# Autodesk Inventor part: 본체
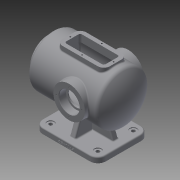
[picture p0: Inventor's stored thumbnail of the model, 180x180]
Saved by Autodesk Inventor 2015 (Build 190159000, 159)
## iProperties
Created: 2021-11
Part Number: 본체
Material: 일반
Document SubType Name: Modeling
Designer: 10259o
Density: 1 g/cm^3
Appearance: 기본값
Author: 10259o
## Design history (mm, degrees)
sketch "스케치1"
  geometry: L1 (80, -65)-(-80, -65); L2 (-80, -65)-(-80, 65); L3 (-80, 65)-(80, 65); L4 (80, 65)-(80, -65); L5 (80, -65)-(-80, 65); L6 (-80, -65)-(80, 65); 1 further point
  constraints: 12 end point, 2 midpoint, 2 parallel, 1 horizontal, 1 perpendicular
  dimensions: "d0" = 160 distance of L1.start L1.end; "d1" = 130 distance of L3.end L1.start
extrude "돌출1" new body sketch "스케치1" distance "d2" = 14; taper "d3" = 0 deg
sketch "스케치10"
  geometry: L1 (0, 0)-(0, 14) reference; 2 further points
  constraints: 1 other
  dimensions: "d49" = 5 distance of point (80, 0) point (80, 5); "d50" = 80 distance from line of L1 point (80, 5)
feature "엠보싱1" sketch "스케치10" dims "d51" = 0.5, "d52" = 0, "d61" = 100, "d62" = 200, "d63" = 65, "d64" = 20, "d65" = 114
sketch "스케치12"
  geometry: L1 (-100, 114)-(100, 114); L2 (100, 114)-(100, 179); L3 (100, 179)-(-75.993, 179); L4 (80, 0)-(80, 14) reference; L5 (80, 0)-(-80, 0) reference; A1 r 100 centre (0, 114) between (-75.993, 179) and (-100, 114); 1 further point
  constraints: 6 end point, 2 perpendicular, 2 point on circle, 1 centre point, 1 horizontal, 1 horizontal alignment
  dimensions: "d61" = 100 radius of A1; "d62" = 200 distance of L1.start L1.end; "d63" = 65 distance of L1.end L2.end; "d64" = 20 distance between parallel lines of L2 L4; "d65" = 114 distance between parallel lines of L1 L5
revolve "회전1" sketch "스케치12" stored, may be unused: angle "d66" = 90 deg
fillet "모깎기1" dims "d67" = 10
feature "쉘1" dims "d68" = 10
sketch "스케치13"
  geometry: C1 r 55 at (0, 0) reference; C2 r 65 at (0, 0) reference; C3 r 55 at (0, 0); 1 further point
  constraints: 1 centre point, 1 coincident
  dimensions: "d69" = 110 diameter of C3
extrude "돌출8" join sketch "스케치13" distance "d70" = 15; taper "d71" = 0 deg
sketch "스케치14"
  geometry: C1 r 65 at (0, 0) reference; C2 r 47.5 at (0, 0); 1 further point
  constraints: 1 centre point, 1 coincident
  dimensions: "d72" = 95 diameter of C2
extrude "돌출9" join sketch "스케치14" distance "d73" = 10; taper "d74" = 0 deg
sketch "스케치15"
  geometry: C1 r 47.5 at (0, 0) reference; C2 r 32.5 at (0, 0); 1 further point
  constraints: 1 centre point, 1 coincident
  dimensions: "d75" = 65 diameter of C2
extrude "돌출10" cut sketch "스케치15" distance "d76" = 25; taper "d77" = 0 deg
sketch "스케치16"
  geometry: C1 r 32.5 at (0, 0) reference; 2 further points
  constraints: 1 vertical alignment
  dimensions: "d78" = 40 distance of C1.centre point (0, 40)
hole "구멍3" sketch "스케치16" at (0, 40) diameter "d79" = 3.242; stored, may be unused: countersink angle "d83" = 90 deg, drill point angle "d85" = 118 deg; dims "d80" = 11, "d81" = 52, "d82" = 18, "d84" = 13
sketch "스케치17"
  geometry: L1 (-71.239, 179)-(100, 179) reference; L2 (100, 179)-(100, 161.5) reference; L3 (100, 161.5)-(110, 161.5) reference; L4 (110, 161.5)-(110, 155.621) reference; L5 (110, 155.621)-(97, 155.621) reference; L6 (97, 155.621)-(96.026, 154) reference; L7 (96.026, 154)-(97, 152.379) reference; L8 (97, 152.379)-(110, 152.379) reference; L9 (110, 152.379)-(110, 146.5) reference; L10 (110, 146.5)-(85, 146.5) reference; L11 (85, 146.5)-(85, 169) reference; L12 (85, 169)-(-71.239, 169) reference; L13 (-71.239, 59)-(85, 59) reference; L14 (85, 59)-(85, 81.5) reference; L15 (85, 81.5)-(110, 81.5) reference; L16 (110, 81.5)-(110, 75.621) reference; L17 (110, 75.621)-(97, 75.621) reference; L18 (97, 75.621)-(96.026, 74) reference; L19 (96.026, 74)-(97, 72.379) reference; L20 (97, 72.379)-(110, 72.379) reference; L21 (110, 72.379)-(110, 66.5) reference; L22 (110, 66.5)-(100, 66.5) reference; L23 (100, 66.5)-(100, 49) reference; L24 (100, 49)-(-71.239, 49) reference; L25 (-80, 0)-(-80, 14) reference; L26 (-80, 14)-(80, 14) reference; L27 (80, 14)-(80, 0) reference; L28 (80, 0)-(-80, 0) reference; C1 r 40 at (-17, 114); A1 r 100 centre (0, 114) between (-79.154, 175.111) and (-79.154, 52.889) reference; A2 r 10 centre (-71.239, 169) between (-71.239, 179) and (-79.154, 175.111) reference; A3 r 90 centre (0, 114) between (-71.239, 169) and (-71.239, 59) reference; A4 r 10 centre (-71.239, 59) between (-79.154, 52.889) and (-71.239, 49) reference; 1 further point
  constraints: 1 centre point
  dimensions: "d89" = 80 diameter of C1; "d90" = 114 distance from line of L28 C1.centre; "d91" = 127 horizontal distance of L16.end C1.centre
extrude "돌출11" join sketch "스케치17" stored distance "d92" = 150; taper "d93" = 0 deg
sketch "스케치18"
  geometry: C1 r 40 at (0, 0) reference; C2 r 21 at (0, 0); 1 further point
  constraints: 1 centre point, 1 coincident
  dimensions: "d94" = 42 diameter of C2
extrude "돌출12" cut sketch "스케치18" distance "d95" = 18; taper "d96" = 0 deg
sketch "스케치19"
  geometry: C1 r 40 at (0, 0) reference; 1 further point
hole "구멍4" sketch "스케치19" at (0, 0) diameter "d97" = 42; stored, may be unused: countersink angle "d101" = 90 deg, drill point angle "d103" = 118 deg; dims "d98" = 11, "d99" = 52, "d100" = 18, "d102" = 13
sketch "스케치20"
  geometry: C1 r 21 at (0, 0) reference; 2 further points
  constraints: 1 vertical alignment
  dimensions: "d104" = 32.5 distance of C1.centre point (0, 32.5)
hole "구멍5" sketch "스케치20" at (0, 32.5) diameter "d105" = 3.242; stored, may be unused: countersink angle "d109" = 90 deg, drill point angle "d111" = 118 deg; dims "d106" = 11, "d107" = 52, "d108" = 18, "d110" = 13
node "작업 평면2"
sketch "스케치21"
  geometry: L1 (60, -30)-(-60, -30); L2 (-60, -30)-(-60, 30); L3 (-60, 30)-(60, 30); L4 (60, 30)-(60, -30); L5 (60, -30)-(-60, 30); L6 (-60, -30)-(60, 30); 1 further point
  constraints: 12 end point, 2 midpoint, 2 parallel, 1 horizontal, 1 perpendicular
  dimensions: "d116" = 120 distance of L2.end L3.end; "d117" = 60 distance of L1.end L2.end
extrude "돌출13" join sketch "스케치21" stored distance "d118" = 18; taper "d119" = 0 deg
fillet "모깎기2" dims "d120" = 15
sketch "스케치22"
  geometry: L1 (-45, 30)-(45, 30) reference; L2 (-60, -15)-(-60, 15) reference; L3 (45, -30)-(-45, -30) reference; L4 (60, 15)-(60, -15) reference; L5 (50, 15)-(50, -15); L6 (45, -20)-(-45, -20); L7 (-50, -15)-(-50, 15); L8 (-45, 20)-(45, 20); A1 r 15 centre (45, 15) between (60, 15) and (45, 30) reference; A2 r 15 centre (-45, 15) between (-45, 30) and (-60, 15) reference; A3 r 15 centre (-45, -15) between (-60, -15) and (-45, -30) reference; A4 r 15 centre (45, -15) between (45, -30) and (60, -15) reference; A5 r 5 centre (45, 15) between (50, 15) and (45, 20); A6 r 5 centre (45, -15) between (45, -20) and (50, -15); A7 r 5 centre (-45, -15) between (-50, -15) and (-45, -20); A8 r 5 centre (-45, 15) between (-45, 20) and (-50, 15); 1 further point
  constraints: 8 end point, 8 point on circle, 4 centre point, 7 other
  dimensions: "d121" = 10 distance between parallel lines of L1 L8
extrude "돌출14" cut sketch "스케치22" distance "d122" = 70; taper "d123" = 0 deg
sketch "스케치23"
  geometry: 2 further points
  constraints: 1 vertical alignment
  dimensions: "d124" = 25 distance of point (0, 0) point (0, 25)
hole "구멍6" sketch "스케치23" at (0, 25) diameter "d125" = 3.242; stored, may be unused: countersink angle "d129" = 90 deg, drill point angle "d131" = 118 deg; dims "d126" = 9, "d127" = 52, "d128" = 18, "d130" = 11
sketch "스케치24"
  geometry: 2 further points
  constraints: 1 horizontal alignment
  dimensions: "d132" = 55 distance of point (0, 0) point (-55, 0)
hole "구멍7" sketch "스케치24" at (-55, 0) diameter "d133" = 3.242; stored, may be unused: countersink angle "d137" = 90 deg, drill point angle "d139" = 118 deg; dims "d134" = 9, "d135" = 52, "d136" = 18, "d138" = 11
sketch "스케치25"
  geometry: L1 (-65.5, 6.971)-(-65.5, 7.385) reference; L2 (-65.5, 7.385)-(-65, 7.385) reference; L3 (-65, 7.385)-(-65, 14) reference; L4 (-65, 14)-(65, 14) reference; L5 (65, 14)-(65, 0) reference; L6 (65, 0)-(-65, 0) reference; L7 (-65, 0)-(-65, 6.971) reference; L8 (-65, 6.971)-(-65.5, 6.971) reference; L9 (-20, 184)-(-20, 165.235) reference; L10 (-41.4, 150.208)-(-20, 150.208) reference; L11 (-20, 150.208)-(-20, 126.329) reference; L12 (-20, 126.329)-(-75, 126.329) reference; L13 (-75, 126.329)-(-75, 150.208) reference; L14 (-75, 150.208)-(-53.981, 150.208) reference; L15 (-30, 171.663)-(-30, 184) reference; L16 (-30, 184)-(-26.621, 184) reference; L17 (-26.621, 184)-(-26.621, 173) reference; L18 (-26.621, 173)-(-25, 172.026) reference; L19 (-25, 172.026)-(-23.379, 173) reference; L20 (-23.379, 173)-(-23.379, 184) reference; L21 (-23.379, 184)-(-20, 184) reference; L22 (20, 165.235)-(20, 184) reference; L23 (20, 184)-(23.379, 184) reference; L24 (23.379, 184)-(23.379, 173) reference; L25 (23.379, 173)-(25, 172.026) reference; L26 (25, 172.026)-(26.621, 173) reference; L27 (26.621, 173)-(26.621, 184) reference; L28 (26.621, 184)-(30, 184) reference; L29 (30, 184)-(30, 171.663) reference; L30 (53.981, 150.208)-(75, 150.208) reference; L31 (75, 150.208)-(75, 133.672) reference; L32 (75, 133.672)-(57, 133.672) reference; L33 (57, 133.672)-(57, 126.329) reference; L34 (57, 126.329)-(20, 126.329) reference; L35 (20, 126.329)-(20, 150.208) reference; L36 (20, 150.208)-(41.4, 150.208) reference; L37 (41.4, 77.792)-(-41.4, 77.792) reference; L38 (-75, 101.671)-(57, 101.671) reference; L39 (57, 101.671)-(57, 94.328) reference; L40 (57, 94.328)-(75, 94.328) reference; L41 (75, 94.328)-(75, 77.792) reference; L42 (75, 77.792)-(53.981, 77.792) reference; L43 (-53.981, 77.792)-(-75, 77.792) reference; L44 (-75, 77.792)-(-75, 101.671) reference; C1 r 55 at (0, 114); A1 r 55 centre (0, 114) between (-20, 165.235) and (-41.4, 150.208) reference; A2 r 65 centre (0, 114) between (-30, 171.663) and (-53.981, 150.208) reference; A3 r 65 centre (0, 114) between (53.981, 150.208) and (30, 171.663) reference; A4 r 55 centre (0, 114) between (41.4, 150.208) and (20, 165.235) reference; A5 r 55 centre (0, 114) between (-41.4, 77.792) and (41.4, 77.792) reference; A6 r 65 centre (0, 114) between (-53.981, 77.792) and (53.981, 77.792) reference; 1 further point
  constraints: 1 centre point, 1 coincident
  dimensions: "d140" = 110 diameter of C1
extrude "돌출15" cut sketch "스케치25" stored distance "d141" = 130; taper "d142" = 0 deg
fillet "모깎기3" dims "d149" = 20
sketch "스케치27"
  geometry: L1 (-60, 65)-(60, 65) reference; L2 (80, 45)-(80, -45) reference; L3 (60, -65)-(-60, -65) reference; L4 (-80, -45)-(-80, 45) reference; A1 r 20 centre (60, 45) between (80, 45) and (60, 65) reference; A2 r 20 centre (-60, 45) between (-60, 65) and (-80, 45) reference; A3 r 20 centre (60, 45) between (80, 45) and (60, 65) reference; A4 r 20 centre (60, -45) between (60, -65) and (80, -45) reference; A5 r 20 centre (-60, -45) between (-80, -45) and (-60, -65) reference; 1 further point
hole "구멍8" sketch "스케치27" at (60, 45) diameter "d150" = 9; stored, may be unused: countersink angle "d154" = 90 deg, drill point angle "d156" = 118 deg; dims "d151" = 8, "d152" = 18, "d153" = 2, "d155" = 14
sketch "스케치28"
  geometry: L1 (100, 161.5)-(110, 161.5) reference; L2 (110, 161.5)-(110, 155.621) reference; L3 (110, 155.621)-(97, 155.621) reference; L4 (97, 155.621)-(96.026, 154) reference; L5 (96.026, 154)-(97, 152.379) reference; L6 (97, 152.379)-(110, 152.379) reference; L7 (110, 152.379)-(110, 146.5) reference; L8 (110, 146.5)-(85, 146.5) reference; L9 (85, 146.5)-(85, 169) reference; L10 (85, 169)-(50, 169) reference; L11 (50, 169)-(50, 184) reference; L12 (50, 184)-(53.379, 184) reference; L13 (53.379, 184)-(53.379, 173) reference; L14 (53.379, 173)-(55, 172.026) reference; L15 (55, 172.026)-(56.621, 173) reference; L16 (56.621, 173)-(56.621, 184) reference; L17 (56.621, 184)-(60, 184) reference; L18 (60, 184)-(60, 179) reference; L19 (60, 179)-(100, 179) reference; L20 (100, 179)-(100, 161.5) reference; L21 (-71.239, 179)-(-60, 179) reference; L22 (-60, 179)-(-60, 184) reference; L23 (-60, 184)-(-56.621, 184) reference; L24 (-56.621, 184)-(-56.621, 173) reference; L25 (-56.621, 173)-(-55, 172.026) reference; L26 (-55, 172.026)-(-53.379, 173) reference; L27 (-53.379, 173)-(-53.379, 184) reference; L28 (-53.379, 184)-(-50, 184) reference; L29 (-50, 184)-(-50, 169) reference; L30 (-50, 169)-(-71.239, 169) reference; L31 (-71.239, 59)-(85, 59) reference; L32 (85, 59)-(85, 81.5) reference; L33 (85, 81.5)-(110, 81.5) reference; L34 (110, 81.5)-(110, 75.621) reference; L35 (110, 75.621)-(97, 75.621) reference; L36 (97, 75.621)-(96.026, 74) reference; L37 (96.026, 74)-(97, 72.379) reference; L38 (97, 72.379)-(110, 72.379) reference; L39 (110, 72.379)-(110, 66.5) reference; L40 (110, 66.5)-(100, 66.5) reference; L41 (100, 66.5)-(100, 49) reference; L42 (100, 49)-(-71.239, 49) reference; L43 (-80, 14)-(80, 14) reference; L44 (80, 14)-(80, 0) reference; L45 (80, 0)-(-80, 0) reference; L46 (-80, 0)-(-80, 14) reference; L47 (-60, 14)-(60, 14) reference; L48 (60, 14)-(47.261, 49); L49 (-69, 14)-(-51, 14) reference; L50 (-60, 14)-(-47.261, 49); L51 (0, 49)-(0, 14); A1 r 100 centre (0, 114) between (-79.154, 175.111) and (-79.154, 52.889) reference; A2 r 10 centre (-71.239, 169) between (-71.239, 179) and (-79.154, 175.111) reference; A3 r 90 centre (0, 114) between (-71.239, 169) and (-71.239, 59) reference; A4 r 10 centre (-71.239, 59) between (-79.154, 52.889) and (-71.239, 49) reference; 1 further point
  constraints: 6 end point, 4 point on line, 2 midpoint, 1 other
  dimensions: "d157" = 60 horizontal distance of point (0, 0) L48.start; "d158" = 70 deg angle of L47 L48; "d159" = 70 deg angle of L47 L50
extrude "돌출17" join sketch "스케치28" stored distance "d160" = 14; taper "d161" = 0 deg
sketch "스케치29"
  geometry: C1 r 21 at (0, 0) reference; C2 r 40 at (0, 0) reference; C3 r 26 at (0, 0); 1 further point
  constraints: 1 centre point, 1 coincident
  dimensions: "d162" = 52 diameter of C3
extrude "돌출18" cut sketch "스케치29" distance "d163" = 18; taper "d164" = 0 deg
fillet "모깎기4" dims "d165" = 0.3
fillet "모깎기5" dims "d166" = 3
fillet "모깎기6" dims "d167" = 10
fillet "모깎기7" dims "d168" = 3
chamfer "모따기1" distance "d169" = 1; stored, may be unused: second distance "d170" = 2, angle "d171" = 45 deg
sketch "스케치30"
  geometry: L1 (60, 62)-(-60, 62) reference; L2 (-77, 45)-(-77, -45) reference; L3 (-60, -62)-(60, -62) reference; L4 (77, -45)-(77, 45) reference; L5 (60, -7)-(-60, -7) reference; L6 (-60, -7)-(-60, 7) reference; L7 (-60, 7)-(60, 7) reference; L8 (60, 7)-(60, -7) reference; L9 (7, -50)-(-7, -50); L10 (-7, -50)-(-7, 50); L11 (-7, 50)-(7, 50); L12 (7, 50)-(7, -50); L13 (7, -50)-(-7, 50); L14 (-7, -50)-(7, 50); C1 r 9 at (-60, -45) reference; C2 r 9 at (-60, 45) reference; C3 r 9 at (60, -45) reference; C4 r 9 at (60, 45) reference; A1 r 17 centre (60, 45) between (77, 45) and (60, 62) reference; A2 r 17 centre (-60, 45) between (-60, 62) and (-77, 45) reference; A3 r 17 centre (-60, -45) between (-77, -45) and (-60, -62) reference; A4 r 17 centre (60, -45) between (60, -62) and (77, -45) reference; 1 further point
  constraints: 12 end point, 2 midpoint, 2 parallel, 1 horizontal, 1 perpendicular
  dimensions: "d172" = 14 distance of L10.end L11.end; "d173" = 100 distance of L11.end L9.start
extrude "돌출19" join sketch "스케치30" stored distance "d174" = 18; taper "d175" = 0 deg
feature "면 기울기1" dims angle "d176" = 20 deg
fillet "모깎기8" dims "d177" = 3
fillet "모깎기9" dims "d178" = 3
node "솔리드1"
pattern_circular "원형 패턴2" dims angle "d87" = 360 deg
pattern_circular "원형 패턴3" dims angle "d113" = 360 deg
mirror "대칭2"
mirror "대칭3"
mirror "대칭4"
mirror "대칭5"
mirror "대칭6"
node "절단 모서리 투영4"
node "절단 모서리 투영5"
node "절단 모서리 투영7"
node "절단 모서리 투영8"
node "절단 모서리 투영9"
other parameters: "d115" = 184
